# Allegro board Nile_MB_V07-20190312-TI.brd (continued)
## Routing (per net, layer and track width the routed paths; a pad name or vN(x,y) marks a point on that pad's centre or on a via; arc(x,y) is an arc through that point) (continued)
V5P0_HUB: length 34.7
  TOP w0.4: C4607.1 31.14,26.41 U3702.1
  INNER LAYER 5 w0.3: v3(30.79,26.17) 30.76,26.17 30.76,26.16 30.71,26.11 28.21,26.11 27.86,25.76 20.76,25.76 20.48,26.04 v3(15.58,26.04)
  INNER LAYER 7 w0.3: v3(15.09,11.32) 15.09,11.59 15.73,12.23 15.73,17.68 17.43,19.38 17.43,21.88 15.68,23.63 15.68,25.94 v3(15.58,26.04)
  INNER LAYER 8 w0.3: v1(14.75,11.38) 14.93,11.38 14.93,11.38 14.99,11.38 15.03,11.33 15.03,11.32 v3(15.09,11.32)
  BOTTOM w0.076: R6678.1 14.75,10.78
  BOTTOM w0.3: 14.75,10.78 v1(14.75,11.38)
  vias: v5(31.01,24.81) v5(31.16,25.11) v5(31.36,25.46) v5(31.36,24.81) v6(31.01,24.81) v6(31.16,25.11) v6(31.36,25.46) v6(31.36,24.81)
VBAT_EX: length 85.3
  TOP w0.076: R6658.2 31.38,35.81
  TOP w0.3: 32.61,19.45 32.63,19.45 v6(32.66,19.41) ; 31.38,35.81 32.92,35.81 33.07,35.66 33.36,35.66 33.36,35.66 v6(33.84,35.19) ; 3.68,17.66 v6(3.68,18.26) v6(3.68,18.86) 3.73,18.81 ; 3.68,17.66 3.68,16.41 5.85,16.41 ; 3.68,17.66 3.83,17.51 5.85,17.51 ; 5.85,18.61 5.65,18.81
  INNER LAYER 3 w0.3: v6(33.84,35.19) 34.03,34.99 34.13,34.99 36.27,32.85 39.47,32.85 39.81,32.51 39.81,32.5 v3(39.8,32.5) ; 17.63,15.73 v3(17.48,15.58) 16.83,15.58 16.43,15.18 v3(16.43,14.08) ; v6(4.56,18.81) 4.91,18.81 5.56,19.46 5.56,21.12 5.35,21.34 5.35,39.94 v3(6.21,40.81) ; v3(32.71,17.46) 32.71,17.86 32.65,17.92 32.65,18.62 32.66,18.63 v6(32.66,19.41)
  INNER LAYER 8 w0.3: v1(7.01,40.57) 6.77,40.81 v3(6.21,40.81) ; 40.03,32.26 v3(39.8,32.5) ; v3(32.71,17.46) 32.95,17.7 32.95,17.75 v2(33.49,18.29) ; 22.78,18.29 v3(21.11,19.96) ; v1(17.2,15.78) 17.4,15.58 v3(17.48,15.58) ; v1(16.58,13.6) 16.58,13.93 v3(16.43,14.08)
  INNER LAYER 8 w0.4: 33.16,18.29 24.2,18.29 ; 34.19,17.59 v2(33.49,18.29)
  INNER LAYER 8 w0.8: 33.16,18.29 v2(33.49,18.29) 37.18,18.29 39.94,15.54 39.94,15.06 39.99,15.01 v1(40.46,15.01)
  INNER LAYER 9 w0.8: v1(41,15.56) 41,16.36 40.96,16.4
  INNER LAYER 9 w1: 40.96,16.4 40.96,20.31
  BOTTOM w0.076: 41.15,14.87 41.15,14.86 41.25,14.77 41.38,14.77 41.48,14.86 41.48,14.87 41.74,14.87 41.86,14.75
  BOTTOM w0.15: 20.78,22.11 21.53,22.11 21.58,22.16 ; 21.58,22.16 21.46,22.16 21.31,22.31 21.31,23.01 ; 21.58,22.16 v1(21.81,22.16) ; C6216.1 21.61,20.76 21.36,20.51 v1(21.31,20.51)
  BOTTOM w0.3: C6274.2 20.75,23.23 C418.1 20.35,23.65 20.35,23.88 ; 20.35,23.88 20.35,24.62 20.33,24.63 U2.7 ; 20.35,23.88 19.9,24.33 C6234.1 19.93,24.45 U2.8 ; U3708.4 17.77,15.28 v1(17.77,15.78) v1(17.2,15.78) ; U3708.2 16.58,13.92 v1(16.58,13.6)
  BOTTOM w1: v1(40.86,14.3) 41.57,14.3
  vias: v1(21.34,21.31) v1(21.34,20.86) v1(21.56,21.41) v1(21.56,21.01) v1(21.61,20.66) v1(21.91,21.36) v1(21.96,20.91) v1(21.96,20.51) v1(40.46,15.41) v1(40.46,14.66) v1(40.46,14.31) v1(40.46,13.96) v1(40.46,13.66) v1(40.86,15.26) v1(40.86,14.96) v1(40.86,14.66) v1(40.86,13.96) v1(40.86,13.66) v1(41.28,15.32) v1(41.21,14.66) v1(41.21,14.36) v1(41.21,14.01) v1(41.21,13.66) v1(41.31,14.93) v1(41.56,14.16) v1(41.61,14.56) v1(41.61,13.76) v2(21.34,21.31) v2(21.34,20.86) v2(21.41,22.11) v2(21.56,21.41) v2(21.56,21.01) v2(21.61,20.66) v2(21.91,21.36) v2(21.96,20.91) v2(21.96,20.51) v2(22.96,20.96) v2(22.96,20.61) v2(32.76,18.26) v2(32.81,18.66) v2(33.11,18.31) v2(33.26,18.66) v2(33.71,18.66) v2(33.91,18.26) v2(34.11,18.66) v2(40.46,15.41) v2(40.46,14.66) v2(40.46,14.31) v2(40.46,13.96) v2(40.46,13.66) v2(40.86,15.26) v2(40.86,14.96) v2(40.86,14.66) v2(40.86,13.96) v2(40.86,13.66) v2(41.21,14.66) v2(41.21,14.36) v2(41.21,14.01) v2(41.21,13.66) v2(41.56,14.16) v2(41.61,14.56) v2(41.61,13.76) v3(20.31,19.86) v3(20.71,19.96) v3(20.91,20.31) v3(22.38,21.73) v3(22.41,21.36) v3(22.46,20.96) v5(2.81,14.16) v5(2.81,13.76) v5(3.16,14.16) v5(3.21,13.81) v5(3.56,14.16) v5(3.56,13.81) v5(3.66,17.66) v5(3.66,17.01) v5(3.66,16.41) v5(4.16,18.81) v5(4.16,18.26) v5(4.11,17.61) v5(4.16,17.06) v5(4.11,16.46) v5(4.51,18.26) v5(4.56,17.56) v5(4.56,17.16) v5(4.61,16.51) v6(2.81,14.16) v6(2.81,13.76) v6(3.16,14.16) v6(3.21,13.81) v6(3.56,14.16) v6(3.56,13.81) v6(3.66,17.66) v6(3.66,17.01) v6(3.66,16.41) v6(4.16,18.81) v6(4.16,18.26) v6(4.11,17.61) v6(4.16,17.06) v6(4.11,16.46) v6(4.51,18.26) v6(4.56,17.56) v6(4.56,17.16) v6(4.61,16.51)
VBATT: length 30.7
  INNER LAYER 8 w0.8: v1(25.11,24.96) 25.11,25.26 26.63,26.78 26.63,33.74 24.76,35.61 v2(24.76,35.86)
  INNER LAYER 8 w1.4: v1(23.91,22.18) 23.98,22.25 24.76,22.25 24.9,22.11 26.13,22.11 28.13,20.11 38.12,20.11
  BOTTOM w0.8: v1(23.91,22.18) 23.91,23.76 v1(25.11,24.96)
  vias: v1(23.46,22.56) v1(23.46,22.26) v1(23.46,21.91) v1(23.81,22.56) v1(23.86,21.86) v1(24.26,22.56) v1(24.26,22.26) v1(24.26,21.91) v1(24.41,36.31) v1(24.46,35.81) v1(24.76,36.31) v1(24.76,35.81) v1(25.11,36.31) v1(25.11,35.81) v1(25.11,26.11) v1(25.11,25.71) v1(25.11,25.36) v2(23.46,22.56) v2(23.46,22.26) v2(23.46,21.91) v2(23.81,22.56) v2(23.86,21.86) v2(24.26,22.56) v2(24.26,22.26) v2(24.26,21.91) v2(24.41,36.31) v2(24.46,35.86) v2(24.76,36.31) v2(25.11,36.31) v2(25.11,35.86) v2(25.11,26.11) v2(25.11,25.71) v2(25.11,25.36)
VBUS2_OUT_5V_EN: length 17.1
  INNER LAYER 5 w0.076: v3(18.16,40.66) 18.7,40.12 20.85,40.12 21.32,39.65 31.62,39.65 31.62,39.66 31.81,39.66 31.81,39.65 32.32,39.65 32.32,39.66
  INNER LAYER 8 w0.076: v3(18.16,40.66) 18.16,40.86 18.81,41.51 v1(18.91,41.51)
  BOTTOM w0.076: U3704.4 18.76,41.41 18.86,41.51 v1(18.91,41.51) R147.1
VBUS_OUT_5V: length 17.1
  INNER LAYER 8 w1: v1(8.41,40.71) 8.41,40.74 8.79,41.11 11.21,41.11 17.31,47.21 v1(17.31,48.01)
  BOTTOM w0.5: USB1.1 19.42,51.15 17.68,49.42 17.42,49.42 TP68.1 v1(17.31,48.01)
  vias: v1(8.16,41.51) v1(8.21,41.16) v1(8.21,40.31) v1(8.56,41.51) v1(8.61,41.16) v1(8.61,40.36) v1(8.91,40.86) v1(8.96,41.51) v1(9.11,41.21) v1(9.16,40.71) v1(9.11,40.31) v1(16.91,48.06) v1(17.06,48.56) v1(17.11,49.31) v1(17.56,48.56) v1(17.61,49.31) v1(17.71,48.06) v1(17.86,48.86) v1(17.91,49.76) v2(8.16,41.51) v2(8.21,41.16) v2(8.21,40.31) v2(8.56,41.51) v2(8.61,41.16) v2(8.61,40.36) v2(8.91,40.86) v2(8.96,41.51) v2(9.11,41.21) v2(9.16,40.71) v2(9.11,40.31) v2(16.91,48.06) v2(17.06,48.56) v2(17.11,49.31) v2(17.56,48.56) v2(17.61,49.31) v2(17.71,48.06) v2(17.86,48.86) v2(17.91,49.76) v2(18.41,49.26)
VDD11D_PM: length 1.4
  BOTTOM w0.203: C273.1 26.75,13.02 26.34,12.6 U18.43
VDD13_BT: length 33.1
  INNER LAYER 8 w0.1: v8(26.34,10.56) 26.09,10.56 26.04,10.51 26.03,10.51 25.87,10.34 25.25,10.34 25.13,10.46 24.87,10.46 24.76,10.34 24.66,10.34
  INNER LAYER 8 w0.127: v8(25.59,9.84) 25.56,9.82 25.17,9.82
  INNER LAYER 8 w0.152: 24.33,9.66 24.47,9.8 25.15,9.8 25.17,9.82
  INNER LAYER 8 w0.2: 24.33,9.66 23.93,9.26 23.44,9.26 v1(23.43,9.27)
  INNER LAYER 8 w0.25: 24.66,10.34 24.42,10.34 23.64,9.56 23.64,9.48 v1(23.43,9.27)
  INNER LAYER 8 w0.3: 22.59,14.97 22.65,14.91 v8(23.29,14.91)
  INNER LAYER 8 w0.35: v8(21.85,8.22) 21.6,8.22 21.54,8.29 21.22,8.29 20.9,8.61 20.9,8.67 ; 20.9,8.67 20.96,8.67 v8(21.55,8.07) 21.55,7.97 21.67,7.86 21.75,7.94 v8(21.83,7.94) ; 20.9,8.67 20.54,9.03 20.54,12.72 20.39,12.87 20.39,13.23 20.54,13.39 20.54,14.2 20.49,14.25 20.49,14.47 20.51,14.48 20.51,14.56 20.91,14.96 22.59,14.96 22.59,14.97 ; 22.59,14.97 22.65,15.03 22.65,15.12 22.59,15.18 22.59,14.97
  INNER LAYER 9 w0.2: v1(23.36,8.7) 23.6,8.94 23.86,8.94 24.47,9.55 24.47,9.64 24.65,9.82 24.7,9.82 24.7,9.82 24.94,9.82 24.95,9.82 v4(25.1,9.82)
  INNER LAYER 9 w0.3: 23.41,14.63 23.57,14.8 23.57,14.89 v8(23.69,14.89) ; 23.57,14.04 23.57,14.59 23.31,14.85
  INNER LAYER 9 w0.35: v1(24.6,13.61) 24,13.61 23.57,14.04
  BOTTOM w0.076: C265.1 25.31,13.61 ; C264.1 23.39,9.92
  BOTTOM w0.2: v4(25.1,9.82) 25.07,9.82 ; 23.4,9.31 23.71,9.62 ; 24.35,10.06 U18.5 ; 23.37,9.27 23.36,9.27 23.36,9.08 ; 23.39,9.92 23.48,9.92 23.65,10.1
  BOTTOM w0.203: 25.7,12.31 25.84,12.16 U18.29 ; 23.71,9.62 23.9,9.62 24.35,10.06 ; U18.4 24.65,10.56 24.64,10.55 24.64,10.55 24.59,10.5 24.29,10.5 23.89,10.1 23.65,10.1
  BOTTOM w0.3: v8(23.29,14.91) 23.38,15 R100.2
  BOTTOM w0.35: 25.7,12.31 25.7,12.7 25.63,12.76 25.63,13.21 25.31,13.53 25.31,13.61 25.31,13.61 v1(24.6,13.61) ; v1(23.36,8.7) 23.36,9.08 23.37,9.09 23.37,9.27 23.4,9.31 23.4,9.91 23.39,9.92
  BOTTOM w0.4: v1(23.36,8.7) 23.36,7.98 v1(23.3,7.93) 21.92,7.93 C258.1
  vias: v8(23.35,15.13) v8(23.65,15.14)
VDD33_FEM: length 32.3
  INNER LAYER 5 w0.3: v3(28.2,11.36) 28.25,11.31 ; 24.03,8.23 24.03,8.22 24.35,7.89 24.35,7.63
  INNER LAYER 5 w0.35: 28.25,11.31 29.35,10.22 29.35,9.02 28.01,7.68 26.86,7.68 26.85,7.69 26.85,7.5 ; v7(24.33,7.43) 24.28,7.48 24.28,7.56 24.35,7.63 24.35,7.62 24.91,7.06 ; 24.91,7.06 26.5,7.06 26.85,7.41 26.85,7.5 ; 24.91,7.06 24.72,7.06 v3(24.54,6.88) ; 26.85,7.5 v7(26.83,7.48)
  INNER LAYER 5 w0.4: 24.04,8.24 24.03,8.23 23.9,8.36 23.9,12.44 v7(23.29,13.05)
  INNER LAYER 8 w0.127: v8(26.83,9.57) 26.83,9.45 26.85,9.43 26.85,9.21 26.83,9.2 26.83,8.82 26.85,8.8 26.85,8.56 26.83,8.54 26.83,8.38 26.69,8.24 26.69,8.17 26.52,8 26.52,7.98 26.55,7.96
  INNER LAYER 8 w0.2: v1(24.38,6.61) 24.4,6.59 v1(24.4,6.31) ; v3(24.54,6.88) 24.54,7.05 24.38,7.21 24.38,7.59 24.34,7.63 ; v8(25.84,9.57) 25.27,9.57 25.1,9.4 25.1,8.96
  INNER LAYER 8 w0.203: 26.5,7.87 26.59,7.96 ; v8(23.36,12.61) 23.36,12.98 v7(23.29,13.05)
  INNER LAYER 8 w0.3: 25.1,8.96 24.35,8.22 24.35,7.68 24.4,7.63 24.38,7.62 24.35,7.62 24.35,7.63 24.34,7.63 24.28,7.57 ; 24.28,7.57 24.28,7.68 24.04,7.93 v1(23.95,7.93) 23.95,8.26 24.04,8.34 ; 24.28,7.57 24.28,7.48 v7(24.33,7.43) ; v3(28.2,11.36) 28.35,11.21 v1(28.35,10.92) ; v4(26.59,7.96) 26.56,7.96 ; 24.38,8.19 24.55,8.02 v1(24.55,7.93)
  INNER LAYER 8 w0.4: v4(26.59,7.96) 26.59,7.95 26.83,7.7 v7(26.83,7.48) ; 24.56,6.6 24.56,6.86 v3(24.54,6.88)
  BOTTOM w0.076: 28.36,10.83 28.37,10.82 C270.1 ; 26.59,7.97 v4(26.59,7.96) C257.1 ; C272.1 23.9,11.93
  BOTTOM w0.1: U18.71 28,11.05 28.23,10.82 28.36,10.82
  BOTTOM w0.2: U18.55 26.58,7.98 26.59,7.97
  BOTTOM w0.203: U18.2 24.59,11.55 ; 23.39,12.58 v8(23.36,12.61)
  BOTTOM w0.25: 28.36,10.82 28.36,10.83 28.16,11.03 27.93,11.03 27.9,11.05
  BOTTOM w0.3: C255.1 23.9,12.01 23.9,11.93 ; v1(23.95,7.93) v1(24.55,7.93)
  BOTTOM w0.35: 24.59,11.55 24.5,11.55 24.3,11.75
  BOTTOM w0.4: 23.33,12.58 23.39,12.58 24.01,11.96 24.01,11.93 24.02,11.92 24.14,11.92 24.3,11.75
  BOTTOM w0.6: C255.1 23.3,12.61 23.3,13.49 R102.2
  vias: v8(23.2,13.52) v8(23.25,13.82)
VDD_CAP: length 14.7
  INNER LAYER 9 w0.076: v1(30.73,37.99) 30.76,37.99 30.76,38.02 30.9,38.02 v2(30.9,38.17)
  BOTTOM w0.3: 11.91,34.41 U4619.6 ; 11.91,34.41 12.44,34.41 12.66,34.19 14.46,34.19 ; 11.91,34.41 11.86,34.36 11.86,33.72 ; C6300.1 15.81,37.16 16.26,37.61 ; C6270.1 16.48,38.11 16.62,37.97
  BOTTOM w1: 14.46,34.19 14.46,34.26 16.26,36.06 16.26,37.61 16.62,37.97 L3709.1
  vias: v1(17.91,38.16) v1(17.91,37.66) v1(18.36,38.16) v1(18.36,37.66) v1(18.81,38.21) v1(18.81,37.66) v1(19.36,37.61) v1(19.41,38.16) v1(19.86,38.16) v1(19.86,37.61) v1(20.36,38.16) v1(20.41,37.61) v1(20.96,38.21) v1(20.96,37.61) v1(30.5,38.17) v1(30.5,37.79) v1(30.5,37.42) v1(30.9,37.77) v1(30.9,37.42) v1(31.3,38.17) v1(31.3,37.77) v1(31.3,37.42) v1(31.65,38.17) v1(31.65,37.77) v1(31.65,37.42) v1(32,38.17) v1(32,37.77) v1(32,37.42) v2(17.91,38.16) v2(17.91,37.66) v2(18.36,38.16) v2(18.36,37.66) v2(18.81,38.21) v2(18.81,37.66) v2(19.36,37.61) v2(19.41,38.16) v2(19.86,38.16) v2(19.86,37.61) v2(20.36,38.16) v2(20.41,37.61) v2(20.96,38.21) v2(20.96,37.61) v2(30.5,38.17) v2(30.5,37.79) v2(30.5,37.42) v2(30.9,37.77) v2(30.9,37.42) v2(31.3,38.17) v2(31.3,37.77) v2(31.3,37.42) v2(31.65,38.17) v2(31.65,37.77) v2(31.65,37.42) v2(32,38.17) v2(32,37.77) v2(32,37.42)
VDDIO_954_EN: length 32.3
  INNER LAYER 3 w0.076: v3(16.91,24.46) 16.91,24.66 18.41,26.16 18.41,36.71 19.21,37.51 19.21,38.31 20.36,39.46 v3(20.46,39.46)
  INNER LAYER 5 w0.076: 30.45,39.42 30.44,39.41 20.51,39.41 v3(20.46,39.46)
  INNER LAYER 8 w0.076: v3(16.91,24.46) 16.91,24.32 17.42,23.81 20.52,23.81 v1(21.1,24.38)
  BOTTOM w0.076: U2.6 20.73,24.75 v1(21.1,24.38)
VIN_8V5: length 19.5
  INNER LAYER 8 w0.8: v2(29.27,44.36) 31.14,46.23 40.53,46.23
  INNER LAYER 9 w0.8: v1(27.8,40.8) 27.8,40.92 29.06,42.18 29.06,44.15 v2(29.27,44.36)
  BOTTOM w0.5: 28.18,41.02 27.9,40.74
  BOTTOM w0.6: B34.1 25.66,40.82 C438.1 27.79,40.82 ; 27.59,41.02 27.79,40.82 ; 27.79,40.82 v1(27.8,40.8)
  vias: v1(27.28,40.6) v1(27.38,40.49) v1(27.79,40.46) v1(28.16,40.47) v1(28.35,40.62) v2(28.98,44.33) v2(29.23,44.08) v2(29.43,44.73) v2(29.64,44.48)
ANT_2G_CH0: length 1.6
  BOTTOM w0.076: C288.2 35.02,6.27
  BOTTOM w0.12: FL1.3 36.2,7 arc(36.03,6.58) L29.2 35.35,6.4 arc(35.17,6.37) 35.02,6.27
BB_PLL_REF_CLK: length 20.2
  INNER LAYER 3 w0.076: v7(30.06,14.38) 31.22,14.38 33.26,16.41 33.26,16.61 34.16,17.51 34.16,18.38 35.96,20.18 35.96,22.66 v3(35.97,22.67)
  INNER LAYER 5 w0.076: v3(35.97,22.67) 36.31,22.33 36.75,22.33 41.96,17.12
  INNER LAYER 8 w0.076: v9(29.85,14.81) 30.06,14.6 v7(30.06,14.38)
BIST_954: length 2.1
  BOTTOM w0.076: R200.1 17.39,23.7
  BOTTOM w0.1: U33.6 16.92,24.95 17.19,24.69 17.19,23.94 17.39,23.73 17.39,23.7
BT_FM_SB_CLK: length 37.5
  INNER LAYER 3 w0.076: v3(29.36,22.61) 29.21,22.46 29.21,21.23 23.89,15.91 23.89,14.92 24.86,13.95 v7(24.98,13.95)
  INNER LAYER 5 w0.076: 37.37,36.12 36.73,35.48 35.2,35.48 34.25,36.43 30.74,36.43 v7(30.61,36.31)
  INNER LAYER 7 w0.076: v7(30.61,36.31) 30.46,36.16 30.46,36.06 30.31,35.91 30.31,35.78 29.76,35.24 29.76,34.41 27.58,32.23 27.58,23.69 28.16,23.11 28.96,23.11 29.36,22.71 v3(29.36,22.61)
  INNER LAYER 8 w0.076: v7(24.98,13.95) 24.98,13.89 25.62,13.25 25.62,12.57 25.61,12.56 25.61,11.81 v8(25.59,11.8)
BT_FM_SB_DATA: length 39.8
  INNER LAYER 3 w0.076: v7(27.14,13.38) 27.06,13.38 26.78,13.1 25.63,13.1 25.2,13.53 25.05,13.53 25.05,13.53 24.97,13.53 23.73,14.77 23.73,15.97 29.05,21.29 29.05,22.42 v3(28.86,22.61)
  INNER LAYER 5 w0.076: 37.48,35.79 36.75,35.06 36.62,35.06 36.62,35.07 35.06,35.07 34.21,35.92 34.2,35.92 34.16,35.96 32.04,35.96 31.99,35.92 31.16,35.92
  INNER LAYER 5 w0.1: v7(29.6,35.5) 30.75,35.5 30.79,35.54 30.79,35.7 30.98,35.88 31.13,35.88 31.16,35.92
  INNER LAYER 7 w0.076: v7(29.6,35.5) 29.51,35.42 29.51,34.71 27.46,32.66 27.46,32.32 27.43,32.29 27.43,23.63 28.45,22.61 v3(28.86,22.61)
  INNER LAYER 8 w0.076: v7(27.14,13.38) 27.14,13.27 27.43,12.99 27.43,12.99 27.62,12.79 v8(27.62,12.75)
  BOTTOM w0.076: v8(27.62,12.75) 27.55,12.75 27.08,12.28 U18.63
CAM2_VDD: length 33.7
  INNER LAYER 5 w0.4: v3(9.56,29.71) 14.83,29.71 15.78,30.67 v3(17.51,30.67)
  INNER LAYER 8 w0.3: v3(17.51,30.67) 17.1,30.67 v8(17,30.77)
  INNER LAYER 8 w0.4: v3(9.56,29.71) 9.56,29.73 9.25,29.73 v1(8.95,30.03) 8.83,30.16 8.01,30.16 6.68,28.83 6.68,28.76 6.46,28.54 6.39,28.54 6.24,28.39 6.24,25.15 6.56,24.82 v1(6.56,22.66) ; v8(17,30.47) v8(17,30.77)
  INNER LAYER 8 w0.8: 20.11,28.41 17.86,30.67 v3(17.51,30.67) 17.41,30.77 v8(17,30.77)
  BOTTOM w0.076: 18.02,27.25 18.03,27.26
  BOTTOM w0.3: 18.03,27.87 18.75,27.87 19.08,27.53 19.95,27.53 C116.1 20.33,27.12 ; 18.03,27.87 R20.2 ; 18.03,27.87 18.03,27.26 18.04,27.25 ; 20.33,27.12 U2.2 ; 20.33,27.12 19.93,26.72 U2.1 19.08,26.28 C115.1 19.09,26.38 19.09,27.03 18.87,27.25 18.04,27.25 ; v8(17,30.47) B2.2 ; 18.04,27.25 R21.2 ; 20.41,26.81 20.52,26.7 20.54,26.71 20.93,26.71 21.13,26.51 U2.4 ; B3.2 6.61,22.65 6.6,22.66 v1(6.56,22.66) ; 17,30.62 v8(17,30.77)
  vias: v1(18.88,26.68) v1(18.88,26.38) v1(19.23,26.68) v1(19.23,26.38) v1(20.31,27.13) v2(18.88,26.68) v2(18.88,26.38) v2(19.23,26.68) v2(19.23,26.38) v2(20.31,27.13)
CAM_MCLK2: length 19.7
  INNER LAYER 5 w0.076: v3(18.41,24.51) 19.26,24.51 19.64,24.13 25.29,24.13 28,21.43 36.46,21.43
  INNER LAYER 8 w0.076: v1(18.09,24.32) 18.22,24.32 v3(18.41,24.51)
CCI_I2C_SCL1: length 25.3
  INNER LAYER 5 w0.076: v3(17.81,27.66) 18.01,27.66 19.85,29.5 25.97,29.5 27.2,28.26 30.72,28.26 30.91,28.06 32.91,28.06 34.66,26.31 34.66,23.71 35.06,23.31 36.48,23.31
  INNER LAYER 8 w0.15: v3(17.81,27.66) 17.81,27.61 v1(17.41,27.21)
  BOTTOM w0.15: U33.2 17.12,26.95 17.41,27.25 17.41,27.21 v1(17.41,27.21)
CCI_I2C_SDA1: length 32.7
  INNER LAYER 5 w0.076: 41.82,18.23 36.55,23.5 35.16,23.5 34.82,23.85 34.82,26.37 32.93,28.26 30.93,28.26 30.78,28.41 27.26,28.41 26.03,29.65 19.7,29.65 18.29,28.24 v3(17.56,28.24)
  INNER LAYER 8 w0.15: v3(17.56,28.24) 17.4,28.08 v1(17.4,27.87)
  BOTTOM w0.076: v1(17.4,27.87) 17.03,27.5 17.02,27.5 16.97,27.45 U33.1
DC_IN: length 25.8
  INNER LAYER 7 w0.2: v7(29.68,46.45) 29.55,46.45 28.36,45.26 28.36,42.81 23.69,38.14 23.69,37.79 v2(23.66,37.76)
  INNER LAYER 8 w0.2: v7(29.68,46.45) 29.77,46.45 30.45,47.13 31.1,47.13 31.1,47.13 31.35,47.13 31.35,47.13 41.09,47.13
  INNER LAYER 9 w0.2: v1(23.98,38.76) 23.98,38.07 v2(23.66,37.76)
  BOTTOM w0.076: C6271.1 v1(23.98,38.76) ; R6579.2 24.55,38.76
  BOTTOM w0.3: v1(23.98,38.76) 24.55,38.76 24.55,37.92 Q2710.1
FAULT_N: length 19.4
  INNER LAYER 3 w0.076: v7(32.9,24.49) 33.1,24.49 33.51,24.91 33.51,25.41 34.09,25.98 34.09,27.52 31.76,29.85 31.76,30.06 31.75,30.07 31.75,33.54 31.75,33.67 31.63,33.79 31.63,36.62 31.54,36.71 31.36,36.89 31.36,39.91 v7(31.96,40.51)
  INNER LAYER 5 w0.076: v7(31.96,40.51) 32.11,40.36
  INNER LAYER 8 w0.076: v8(31.82,24.39) 31.88,24.33 32.73,24.33 v7(32.9,24.49)
IDX_954: length 1.8
  BOTTOM w0.076: R199.1 8.17,27.75
  BOTTOM w0.25: U33.35 8.97,26.95 8.17,27.75
KEY_VOLP_N: length 35.2
  INNER LAYER 5 w0.076: v3(5.76,21.51) 5.76,24.01 8.79,27.03 14.84,27.03 14.98,27.17 15.48,27.17 15.48,27.17 18.37,27.17 18.54,27.33 21.04,27.33 21.29,27.59 29.44,27.59 30.29,26.73 31.74,26.73 31.83,26.64 v7(32,26.64)
  INNER LAYER 8 w0.076: v1(6.54,20.76) 6.51,20.76 ; 6.51,20.76 v3(5.76,21.51) ; 6.51,20.76 6.51,20.66 5.98,20.13 5.43,20.13 4.4,19.1 v1(4.4,18.93) ; v7(32,26.64) 31.82,26.45 v1(31.82,26.29)
LED_EN: length 11.6
  INNER LAYER 3 w0.076: v6(31.18,32.46) 31.16,32.45 31.16,29.71 31.26,29.61 v3(31.26,29.51)
  INNER LAYER 5 w0.076: v3(31.26,29.51) 31.36,29.51 31.71,29.16 32.84,29.16 37.27,24.74 37.27,24.13
LNA_EN_5G_CH0: length 15.2
  INNER LAYER 5 w0.076: v3(25,6.32) 25.06,6.26 27.13,6.26 27.13,6.26 27.38,6.26 27.38,6.26 28.25,6.26 28.82,6.83 29.58,6.83 29.78,6.63 30.63,6.63 31.23,7.23 31.23,7.27 v3(33.55,7.27)
  INNER LAYER 8 w0.076: v3(33.55,7.27) 33.74,7.45 v1(33.74,7.72)
  INNER LAYER 8 w0.1: v3(25,6.32) 25.4,6.72 25.4,8.1 25.55,8.25 25.55,8.42 26.09,8.96 26.09,10.08 26.11,10.1 v8(26.11,10.27)
  BOTTOM w0.1: U22.6 33.03,8.09 33.15,7.97 33.15,7.96 33.3,7.82 33.3,7.82 33.4,7.72 v1(33.74,7.72) ; U18.39 26.11,10.29 26.11,10.27 v8(26.11,10.27)
LPI_UART_1_RX: length 40.9
  INNER LAYER 5 w0.076: v7(26.86,35.16) 27.07,34.95 30.47,34.95 30.78,35.25 34.43,35.25 34.94,34.74 36.87,34.74 37.62,35.49
  INNER LAYER 7 w0.076: v7(22.15,11.17) 22.25,11.26 22.25,11.52 22.55,11.82 22.55,19.59 23.17,20.2 23.17,20.32 23.17,23.52 23.08,23.61 22.55,24.13 22.55,25.54 25.85,28.83 25.85,30 25.86,30.02 25.86,33.76 26.86,34.76 v7(26.86,35.16)
  INNER LAYER 8 w0.076: v2(22.53,11.28) 22.27,11.28 v7(22.15,11.17)
  INNER LAYER 9 w0.076: v2(22.53,11.28) 22.65,11.16 v1(22.83,11.16)
  BOTTOM w0.064: 24.85,11.01 U18.3
  BOTTOM w0.076: v1(22.83,11.16) 23.03,10.97 24.27,10.97 24.31,10.92 24.49,10.92 24.58,11.01 24.85,11.01
LPI_UART_1_TX: length 41.6
  INNER LAYER 5 w0.076: v3(26.36,35.21) 26.36,35.16 26.8,34.72 30.46,34.72 30.85,35.1 34.36,35.1 34.88,34.58 36.93,34.58 37.69,35.34
  INNER LAYER 7 w0.076: v3(26.36,35.21) 26.16,35.01 26.16,34.46 25.69,33.99 25.69,28.89 22.39,25.59 22.39,24.08 23.01,23.46 23.01,20.26 22.39,19.64 22.39,15.39 22.4,15.38 22.4,12.81 21.95,12.37 v7(21.95,12.28)
  INNER LAYER 8 w0.076: v8(25.59,11.3) 25.11,11.3 25.08,11.32 24.98,11.32 24.73,11.57 24.73,11.58 24.64,11.67 24.23,11.67 24.15,11.75 v2(24.15,11.76) ; v7(21.95,12.28) 22.18,12.28 22.39,12.07 v2(22.65,12.07)
  INNER LAYER 9 w0.076: v2(24.15,11.76) 24.15,11.75 23.88,11.75 23.62,12.02 22.7,12.02 v2(22.65,12.07)
MIPI_CSI1_CLK_M: length 33.9
  INNER LAYER 5 w0.076: v7(18.35,21.49) 18.48,21.37 18.93,21.37 19.05,21.49 19.05,22.5 19.27,22.72 19.84,22.72 20.05,22.5 20.05,21.32 19.55,20.81 19.55,20.57 19.95,20.57 20.45,21.07 20.45,22.45 20.67,22.67 21.19,22.67 21.41,22.45 21.41,20.8 22.09,20.12 36.37,20.12 41.92,14.57
  INNER LAYER 8 w0.06: v9(18.02,21.6) 18.24,21.6 v7(18.35,21.49)
MIPI_CSI1_CLK_M_R: length 2
  BOTTOM w0.06: U33.11 16.62,22.45 16.75,22.32 16.9,22.32 17.15,22.07 17.15,21.47 17.2,21.42 17.34,21.42 F2820.4
MIPI_CSI1_CLK_P: length 34.1
  INNER LAYER 5 w0.076: 41.83,14.37 36.29,19.92 22,19.92 21.2,20.72 21.2,22.37 21.1,22.47 20.8,22.47 20.7,22.37 20.7,20.97 20.05,20.32 19.35,20.32 19.3,20.37 19.3,20.92 19.85,21.46 19.85,22.42 19.75,22.52 19.35,22.52 19.25,22.42 19.25,21.41 18.96,21.12 18.5,21.12 18.35,20.97 v7(18.33,20.97)
  INNER LAYER 8 w0.06: v7(18.33,20.97) 18.33,21.08 v9(18.02,21.08)
  BOTTOM w0.06: F2820.2 v9(18.02,21.08)
MIPI_CSI1_CLK_P_R: length 1.9
  BOTTOM w0.06: U33.12 16.59,21.95 16.73,22.09 16.83,22.09 16.95,21.97 16.95,21.4 17.13,21.23 17.35,21.23 17.48,21.1 F2820.3
MIPI_CSI1_L0_DATA_M: length 35.9
  INNER LAYER 5 w0.076: v7(16.55,20.97) 16.55,20.75 16.52,20.72 16.52,20.61 16.76,20.37 17.16,20.37 17.17,20.37 17.48,20.37 17.55,20.44 17.55,21.79 17.48,21.87 16.87,21.87 16.55,22.18 16.55,23.2 16.75,23.4 16.87,23.52 25.2,23.52 27.69,21.02 36.33,21.02 36.45,20.9 42.26,15.09
  INNER LAYER 8 w0.06: v9(16.4,19.56) 16.35,19.61 16.35,20.37 16.55,20.57 v7(16.55,20.97)
MIPI_CSI1_L0_DATA_M_R: length 1.6
  BOTTOM w0.06: F2822.4 16.25,20.21 16.25,20.37 15.65,20.97 15.65,21.21 U33.13
MIPI_CSI1_L0_DATA_P: length 35.8
  INNER LAYER 5 w0.076: v7(16.1,20.67) 16.1,20.74 16.68,20.17 17.08,20.17 17.09,20.16 17.56,20.16 17.76,20.36 17.76,21.87 17.56,22.07 16.95,22.07 16.75,22.27 16.75,23.12 16.95,23.31 25.11,23.31 27.61,20.82 36.25,20.82 42.18,14.88
  INNER LAYER 8 w0.06: v9(15.91,19.55) 16.15,19.79 16.15,20.62 v7(16.1,20.67)
MIPI_CSI1_L0_DATA_P_R: length 1.6
  BOTTOM w0.06: U33.14 15.24,21.08 16.05,20.27 16.05,20.19 F2822.3
MIPI_CSI1_L1_DATA_M: length 35.1
  INNER LAYER 5 w0.076: v7(15.15,20.12) 15.1,20.12 15.1,19.97 14.75,19.62 14.35,19.62 14.01,19.96 14.01,20.17 13.98,20.21 13.76,20.21 13.67,20.11 13.67,19.49 13.77,19.39 15.26,19.39 arc(15.32,19.42) 15.34,19.48 15.34,19.69 arc(15.43,19.78) 15.52,19.69 15.52,19.48 arc(15.61,19.39) 15.7,19.48 15.7,19.67 arc(15.78,19.76) 15.87,19.67 15.87,19.48 arc(15.9,19.42) 15.96,19.39 36.38,19.39 41.76,14.01
  INNER LAYER 8 w0.06: v7(15.15,20.12) 15.15,20.07 15.04,19.95 15.04,19.61 15.1,19.55 v9(15.19,19.55)
MIPI_CSI1_L1_DATA_M_R: length 1.5
  BOTTOM w0.076: F2818.4 15.02,20.22 15.02,20.47 14.65,20.84 14.65,21.21 U33.15
MIPI_CSI1_L1_DATA_P: length 34.3
  INNER LAYER 5 w0.076: v7(14.7,20.22) 14.75,20.17 14.75,19.97 14.65,19.87 14.39,19.87 14.22,20.04 14.22,20.26 14.06,20.41 13.68,20.41 13.46,20.2 13.46,19.41 13.68,19.19 36.3,19.19 41.68,13.81
  INNER LAYER 8 w0.06: v9(14.69,19.55) 14.79,19.55 14.85,19.61 14.85,19.97 14.65,20.17 v7(14.7,20.22)
MIPI_CSI1_L1_DATA_P_R: length 1.5
  BOTTOM w0.076: F2818.3 14.81,20.17 14.81,20.44 14.24,21.01 U33.16
MIPI_CSI1_L2_DATA_M: length 34.3
  INNER LAYER 5 w0.076: v7(11.55,19.92) 11.45,19.82 11.45,19.72 11.65,19.52 11.75,19.52 12.11,19.87 12.45,19.87 12.66,19.67 12.66,19 12.83,18.82 36.11,18.82 41.74,13.19
  INNER LAYER 8 w0.06: v9(11.5,19.57) 11.5,19.87 v7(11.55,19.92)
MIPI_CSI1_L2_DATA_M_R: length 1.4
  BOTTOM w0.076: U33.21 11.74,21.05 11.5,20.81 11.5,20.57 11.35,20.42 11.35,20.23 F2821.4
MIPI_CSI1_L2_DATA_P: length 34.7
  INNER LAYER 5 w0.076: v7(11.05,19.92) 11.2,19.77 11.2,19.62 11.55,19.27 11.79,19.27 12.19,19.67 12.37,19.67 12.45,19.58 12.45,18.92 12.75,18.62 36.03,18.62 41.66,12.99
  INNER LAYER 8 w0.06: v9(11,19.57) 11,19.87 v7(11.05,19.92)
MIPI_CSI1_L2_DATA_P_R: length 1.4
  BOTTOM w0.076: F2821.3 11.19,20.27 11.19,20.48 11.34,20.63 11.34,20.96 11.24,21.06 U33.22
MIPI_CSI1_L3_DATA_M: length 35.4
  INNER LAYER 5 w0.076: v7(10.2,19.22) 10.25,19.17 10.25,19.02 10.35,18.92 10.53,18.92 arc(10.59,18.94) 10.62,19 10.62,19.13 arc(10.71,19.22) 10.79,19.13 10.79,19 arc(10.88,18.92) 10.97,19 10.97,19.13 arc(11.06,19.22) 11.15,19.13 11.15,18.97 arc(11.16,18.93) 11.2,18.92 11.25,18.92 11.41,18.76 12.06,18.76 12.56,18.27 35.8,18.27 41.48,12.59
  INNER LAYER 8 w0.06: v7(10.2,19.22) 10.24,19.25 v9(10.24,19.59)
MIPI_CSI1_L3_DATA_M_R: length 1.5
  BOTTOM w0.076: F2819.4 10.11,20.22 10.11,20.27 10.61,20.77 10.61,20.93 10.74,21.06 U33.23
MIPI_CSI1_L3_DATA_P: length 34.8
  INNER LAYER 5 w0.076: v7(9.73,19.19) 10.25,18.67 10.99,18.67 11.2,18.67 11.31,18.56 11.98,18.56 12.52,18.02 35.71,18.02 41.34,12.39
  INNER LAYER 8 w0.06: v7(9.73,19.19) 9.74,19.2 v9(9.74,19.59)
MIPI_CSI1_L3_DATA_P_R: length 1.5
  BOTTOM w0.076: F2819.3 9.74,20.12 10.37,20.75 10.37,20.95 10.24,21.08 U33.24
MIPI_DSI0_CLK_M: length 10.7
  INNER LAYER 3 w0.07: v7(46.58,41.09) 46.6,41.11 46.6,41.26 46.68,41.34 46.81,41.34 46.92,41.23 46.92,40.52 46.84,40.44 45.26,40.44 45.01,40.19 45.01,39.59 45.29,39.31 47.5,39.31 50.13,36.68
  INNER LAYER 8 w0.07: v9(46.84,41.43) 46.84,41.35 v7(46.58,41.09)
MIPI_DSI0_CLK_P: length 10.8
  INNER LAYER 3 w0.07: 50.33,36.76 47.59,39.51 45.38,39.51 45.21,39.67 45.21,40.11 45.34,40.24 46.92,40.24 47.12,40.44 47.12,41.31 46.9,41.53 46.9,41.54 46.89,41.55 46.7,41.55 46.6,41.66 v7(46.6,41.73)
  INNER LAYER 8 w0.07: v7(46.6,41.73) 46.56,41.7 46.56,41.65 v9(46.34,41.43)
MOD_AP_READY: length 14.2
  TOP w0.076: TP100.1 v6(33.61,19.86)
  INNER LAYER 3 w0.076: v3(35.47,24.03) 35.78,23.72 35.78,23.39 35.36,22.97 35.36,21.71 33.9,20.24 33.9,20.14 v6(33.61,19.86)
  INNER LAYER 5 w0.076: v3(35.47,24.03) 35.38,24.03 35.55,23.86 36.63,23.86 41.92,18.57
MOD_POWER_ON: length 43.3
  INNER LAYER 3 w0.076: v3(13.41,25.71) 13.41,29.26 12.61,30.06 12.61,32.37 13.1,32.86 13.1,35.93 13.8,36.63 v3(13.8,36.82)
  INNER LAYER 5 w0.076: 36.54,21.79 28.06,21.79 25.33,24.53 20.89,24.53 19.88,25.54 13.73,25.54 13.56,25.71 v3(13.41,25.71)
  INNER LAYER 8 w0.076: v1(8.51,36.91) 8.66,36.76 9.21,36.76 9.28,36.7 9.53,36.7 9.59,36.76 13.74,36.76 v3(13.8,36.82)
  BOTTOM w0.076: 8.51,36.9 v1(8.51,36.91) R6537.2
  BOTTOM w0.3: 8.51,36.9 9.58,36.9 Q8.1
MOD_POWER_ON_R: length 27.3
  TOP w0.1: 30.75,35.81 30.75,35.8 29.01,34.06 28.1,34.06 28.05,34.01
  TOP w0.3: 28.05,34.01 28.95,34.01 v6(30.75,35.81)
  INNER LAYER 3 w0.1: v3(27.91,37.26) 28.06,37.41 28.96,37.41 30.56,35.81 v6(30.75,35.81)
  INNER LAYER 5 w0.1: v3(27.91,37.26) 11.76,37.26 v3(11.71,37.31)
  INNER LAYER 8 w0.1: v3(11.71,37.31) 11.91,37.51 v1(11.91,37.81)
MOD_RESET: length 17.6
  TOP w0.1: v5(31.36,20.07) 31.36,21.11 Q2712.1
  INNER LAYER 2 w0.076: v5(31.36,20.07) 32.11,20.82 33.41,20.82 v6(33.64,20.59)
  INNER LAYER 3 w0.076: v3(35.47,24.52) 35.44,24.52 35.17,24.25 35.17,23.3 34.62,22.75 34.62,21.56 v6(33.64,20.59)
  INNER LAYER 5 w0.076: v3(35.47,24.52) 35.48,24.51 35.71,24.51 36.21,24.01 36.69,24.01 37.26,23.45 37.29,23.45 42.02,18.72
MOD_RESET_R: length 23.7
  TOP w0.076: 28.05,37.31 28.19,37.45 31.03,37.45 31.51,36.96 v6(31.66,36.96) ; R6656.2 32.61,20.07 ; Q2712.3 32.16,23.61 32.31,23.76 32.71,23.76 v6(32.81,23.86) ; C437.2 32.01,20.07
  TOP w0.1: 32.61,20.07 32.01,20.07 31.96,20.12 31.96,23.36 Q2712.3
  INNER LAYER 3 w0.076: v6(31.66,36.96) 31.66,36.8 31.78,36.69 31.78,33.85 31.92,33.72 31.92,29.91 34.24,27.58 34.24,25.92 33.67,25.35 33.67,24.84 33.15,24.33 33.15,24.3 32.81,23.96 v6(32.81,23.86)
MOD_RI: length 20.1
  TOP w0.076: 30.36,25.27 R6536.2
  TOP w0.1: v6(30.96,28.5) 30.81,28.35 30.81,26.94 30.36,26.49 30.36,25.27
  INNER LAYER 3 w0.1: v3(31.27,28.56) 31.02,28.56 v6(30.96,28.5)
  INNER LAYER 5 w0.076: 41.85,18.42 36.62,23.65 35.23,23.65 34.97,23.91 34.97,26.44 32.94,28.46 31.37,28.46 v3(31.27,28.56)
MOD_V_BACK: length 3.7
  TOP w0.4: 31.09,16.69 C6366.1
  TOP w0.5: C6366.1 30.61,16.56 29.46,15.41 28.15,15.41 28.05,15.31
MOD_VINT: length 25.1
  TOP w0.076: v6(33.31,36.26) 33.16,36.41 32.66,36.41 32.63,36.45 32.41,36.45 R6663.1
  TOP w0.1: 30.95,17.96 v6(30.95,18.01)
  TOP w0.2: 28.05,17.51 28.76,17.51 29.21,17.96 30.95,17.96
  INNER LAYER 3 w0.1: v6(30.95,18.01) 30.95,20.25 32.11,21.41 32.11,22.71 33.06,23.65 33.06,23.98 33.31,24.24 33.31,24.26 33.66,24.61 34.16,24.61 34.41,24.86 34.41,27.85 33.16,29.1 33.16,31.11 33.78,31.72 33.78,34.38 33.31,34.84 v6(33.31,36.26)
MOD_W_DISABLE: length 7.1
  INNER LAYER 3 w0.076: v3(36.11,24.61) 35.93,24.43 35.93,23.31 35.52,22.89 35.52,21.65 34.05,20.18 34.05,19.35 33.56,18.86 v6(33.56,18.76)
  INNER LAYER 5 w0.076: v3(36.11,24.61) 36.35,24.61
MODE_954: length 2.3
  BOTTOM w0.076: R196.2 9.18,29.46 9.18,29.47 ; 9.58,29.47 R198.1
  BOTTOM w0.25: 9.18,29.47 9.62,29.47 9.62,29.16 10.24,28.55 U33.37
MSS_LTE_COEX_RX: length 9.1
  INNER LAYER 5 w0.076: v7(30.67,11.76) 30.87,11.56 32.25,11.56 34.31,9.51 34.36,9.51 34.9,8.96
  INNER LAYER 8 w0.076: v9(29.09,11.76) 29.2,11.76 29.21,11.76 29.21,11.79 29.35,11.93 29.54,11.93 29.55,11.92 29.86,11.92 30,12.06 30.25,12.06 30.43,11.88 30.43,11.87 30.54,11.76 v7(30.67,11.76)
  BOTTOM w0.076: U18.70 27.61,11.55 27.62,11.53 27.75,11.53 27.75,11.53 27.81,11.53 27.81,11.52 28.39,11.52 28.49,11.62 28.95,11.62 v9(29.09,11.76)
MSS_LTE_COEX_TX: length 10.3
  INNER LAYER 5 w0.076: v7(31.3,12.77) 31.3,12.49 31.7,12.09 31.7,12.09 31.88,11.91 31.88,11.91 31.91,11.88 32.36,11.88 34.43,9.81 34.5,9.81 35.04,9.27
  INNER LAYER 8 w0.076: v8(26.89,11.54) 27.05,11.7 27.6,11.7 28.41,12.52 30.49,12.52 30.69,12.72 31.25,12.72 v7(31.3,12.77)
  BOTTOM w0.076: v8(26.89,11.54) U18.57
PA_EN_5G_CH0: length 9.7
  INNER LAYER 8 w0.076: 33.75,9.08 33.72,9.05 ; 33.75,9.08 v9(33.75,9) ; 33.75,9.08 33.77,9.1 33.77,9.67 31.99,11.45 28.54,11.45 28.51,11.48 28.51,11.49 28.33,11.67 28.08,11.67 27.9,11.49 27.9,11.48 27.81,11.39 27.66,11.39 27.65,11.38 27.59,11.38 27.27,11.05 v8(26.83,11.05)
  BOTTOM w0.1: U22.4 33.25,8.79 arc(33.52,8.85) v9(33.75,9)
PDB_954: length 43
  INNER LAYER 3 w0.076: v3(10.36,38.21) 10.36,36.21 10.01,35.86 10.01,25.71 v3(9.16,24.86)
  INNER LAYER 5 w0.076: 32.26,39.81 32.25,39.81 31.88,39.81 31.87,39.81 31.56,39.81 31.55,39.81 21.38,39.81 20.91,40.27 19.09,40.27 18.3,41.06 13.01,41.06 10.26,38.31 v3(10.36,38.21)
  INNER LAYER 8 w0.076: v2(8.36,23.86) 9.16,24.66 v3(9.16,24.86)
  INNER LAYER 9 w0.076: v1(7.79,23.71) 7.94,23.86 v2(8.36,23.86)
  BOTTOM w0.076: R195.2 7.23,22.66
  BOTTOM w0.25: U33.30 8.96,24.45
  BOTTOM w0.3: 7.23,22.66 7.23,23.15 v1(7.79,23.71) 8.53,24.45 8.96,24.45
PM_RESIN_N: length 40.1
  INNER LAYER 5 w0.076: 13.71,44.86 18.01,44.86 19.65,46.5 22.64,46.5 23.13,46.99 41.31,46.99 41.46,47.14 41.78,47.14 41.93,46.99
  INNER LAYER 5 w0.1: 13.71,44.86 11.16,42.31 10.86,42.31 7.51,38.96 v3(6.76,38.96)
  INNER LAYER 8 w0.1: v3(6.76,38.96) 6.89,38.96 v1(7.06,38.78)
  BOTTOM w0.076: R284.1 6.7,37.91
  BOTTOM w0.1: v1(7.06,38.78) 6.99,38.78 6.7,38.5 6.7,37.91
PON_OUT: length 19.2
  INNER LAYER 3 w0.076: v7(33.1,25.27) 33.94,26.1 33.94,27.46 31.61,29.78 31.61,30 31.6,30.01 31.6,33.6 31.48,33.73 31.48,36.56 31.21,36.82 31.21,39.97 31.6,40.36 31.6,40.58 v7(31.51,40.66)
  INNER LAYER 5 w0.076: v7(31.51,40.66) 31.69,40.66 31.84,40.81 32.09,40.81 32.27,40.64 32.27,40.55
  INNER LAYER 8 w0.076: v7(33.1,25.27) v8(32.87,25.04)
  BOTTOM w0.076: U11.33 v8(32.87,25.04)
QCS_GPIO_76: length 27.9
  INNER LAYER 3 w0.076: v3(11.01,38.51) 10.91,38.41 10.91,38.19 10.91,38.19 10.91,37.94 10.91,37.94 10.91,36.29 10.26,35.64 10.26,24.62 8.77,23.14 v3(8.77,23.1)
  INNER LAYER 5 w0.076: 21.22,39.24 20.94,38.96 11.47,38.96 v3(11.01,38.51)
  INNER LAYER 8 w0.076: v9(8.99,23.33) 8.83,23.17 8.8,23.17 8.77,23.14 v3(8.77,23.1)
  BOTTOM w0.076: v9(8.99,23.33) 9.16,23.5 9.55,23.5 U33.28
QCS_GPIO_77: length 27.4
  INNER LAYER 3 w0.076: v3(9.08,22.72) 10.41,24.05 10.41,35.58 11.06,36.23 11.06,36.36 11.06,38.01 11.12,38.07 v3(11.21,38.07)
  INNER LAYER 5 w0.076: 21.34,38.94 21.06,38.66 12.2,38.66 11.6,38.07 v3(11.21,38.07)
  INNER LAYER 8 w0.076: v9(9.39,22.95) 9.16,22.72 v3(9.08,22.72)
  BOTTOM w0.076: v9(9.39,22.95) U33.27
QCS_GPIO_78: length 27.8
  INNER LAYER 3 w0.076: v3(9.12,22.27) 9.12,22.34 10.56,23.77 10.56,35.52 11.21,36.17 11.21,36.42 11.21,37.6 11.61,38 11.61,38.51 v3(11.56,38.56)
  INNER LAYER 5 w0.076: v3(11.56,38.56) 11.82,38.81 21,38.81 21.28,39.09
  INNER LAYER 8 w0.076: v3(9.12,22.27) 9.16,22.27 9.35,22.45 v9(9.38,22.45)
  BOTTOM w0.076: v9(9.38,22.45) U33.26
QCS_GPIO_91: length 41.7
  INNER LAYER 5 w0.076: v3(6.86,30.36) 7.01,30.36 8,29.37 15.57,29.37 16.21,30.01 18.86,30.01 19.08,29.8 27.78,29.8 27.99,29.58 30.74,29.58 31.46,28.86 32.93,28.86 37.11,24.67 37.11,24.07 41.59,19.59 41.59,19.59
  INNER LAYER 8 w0.076: v1(6.81,29.81) 7.01,30.01 7.01,30.21 v3(6.86,30.36)
  BOTTOM w0.076: R289.1 6.71,28.97 ; 6.84,29.84 D3848.1
  BOTTOM w0.3: D3848.1 6.71,29.73 6.71,28.97
QCS_GPIO_92: length 3.5
  INNER LAYER 5 w0.076: v7(28.06,3.87) 28.06,4.63 28.64,5.21 29.18,5.21 29.27,5.29
  INNER LAYER 8 w0.076: v7(28.06,3.87) 27.9,3.7 27.69,3.7 v1(27.64,3.75)
  BOTTOM w0.076: R288.1 27.56,3.67 v1(27.64,3.75)
QUP6_HCI_UART_CTS_N: length 17.6
  INNER LAYER 5 w0.076: v7(30.79,13.06) 30.88,13.14 31.53,13.14 34.56,10.11 41.96,10.11
  INNER LAYER 8 w0.051: 26.89,11.85 26.89,11.85
  INNER LAYER 8 w0.064: 26.89,11.85 26.6,11.56 26.6,11.44 26.58,11.42 v8(26.58,11.3)
  INNER LAYER 8 w0.076: 26.89,11.85 27.5,11.85 28.05,12.41 28.09,12.41 28.35,12.67 28.36,12.67 28.46,12.77 30.3,12.77 30.35,12.82 30.57,12.82 30.8,13.05 30.8,13.06 v7(30.79,13.06)
QUP6_HCI_UART_RFR_N: length 31.4
  INNER LAYER 3 w0.076: v7(41.83,9.8) 41.82,9.8 41.82,9.83 42.01,10.02 42.01,10.71 49.34,18.03 49.45,18.03 49.73,18.31 49.84,18.31 50.51,18.99 50.51,20.06 51.12,20.67 51.22,20.67
  INNER LAYER 5 w0.076: v7(41.83,9.8) 41.82,9.8 41.82,9.83 41.75,9.9 34.67,9.9 34.65,9.92 34.6,9.92 34.57,9.96 34.5,9.96 31.89,12.57 31.8,12.57 31.75,12.52 31.75,12.5 v7(31.74,12.5)
  INNER LAYER 8 w0.076: v8(27.08,11.3) 27.27,11.3 27.51,11.54 27.59,11.54 27.6,11.55 27.66,11.55 28.48,12.37 30.55,12.37 30.65,12.46 31.7,12.46 v7(31.74,12.5)
QUP6_HCI_UART_RX: length 21.7
  INNER LAYER 3 w0.076: 42.02,8.79 35.31,8.79 34.64,8.12 33.43,8.12 33.33,8.22 31.26,8.22 31.25,8.24 30.88,8.24 30.68,8.43 v3(30.6,8.43)
  INNER LAYER 6 w0.076: v3(24.5,12.02) 25.7,12.02 26.63,11.08 26.63,10.43 28.93,8.14 30.49,8.14 30.6,8.25 v3(30.6,8.43)
  INNER LAYER 8 w0.076: v3(24.5,12.02) 24.5,12.27 v2(24.35,12.42)
  INNER LAYER 9 w0.076: v2(24.35,12.42) 24.4,12.37 24.45,12.17 v1(24.45,12.16)
  BOTTOM w0.076: U18.8 24.74,11.8 24.45,12.09 v1(24.45,12.16)
QUP6_HCI_UART_TX: length 22.4
  INNER LAYER 3 w0.076: v3(31.13,8.54) 31.29,8.38 33.39,8.38 33.49,8.28 34.59,8.28 35.25,8.95 41.96,8.95
  INNER LAYER 5 w0.076: 31.08,8.58 31.13,8.54 v3(31.13,8.54)
  INNER LAYER 6 w0.076: v3(31.13,8.54) 31.13,8.38 30.73,7.98 28.87,7.98 26.48,10.37 26.48,11.02 25.87,11.63 25.1,11.63 v7(25.06,11.67)
  INNER LAYER 8 w0.076: v7(25.06,11.67) 25.22,11.55 v8(25.35,11.55)
  INNER LAYER 9 w0.076: v8(25.35,11.55) 25.32,11.52 23.9,11.52 23.75,11.67 23.6,11.67 v1(23.5,11.77)
  BOTTOM w0.076: R253.2 23.45,11.72 v1(23.5,11.77)
RIN0_M: length 32.8
  INNER LAYER 3 w0.075: v3(13.3,30.28) 13.3,30.35 ; 27.19,54.27 v7(27.35,54.43)
  INNER LAYER 3 w0.076: 13.3,30.35 12.97,30.69 12.97,31.68 13.89,32.6 13.89,35.26 27.19,48.57 27.19,54.27
  INNER LAYER 8 w0.076: v3(13.3,30.28) 13.17,30.28 v1(12.92,30.03)
  INNER LAYER 8 w0.1: v1(27.62,54.81) 27.62,54.7 v7(27.35,54.43)
  INNER LAYER 8 w0.3: 28.84,54.66 27.77,54.66 27.55,54.43 v7(27.35,54.43)
RIN0_P: length 33.3
  INNER LAYER 3 w0.075: v3(13.69,31.15) 13.69,31.2
  INNER LAYER 3 w0.076: v7(28.14,52.19) 27.75,51.79 27.75,48.33 14.45,35.03 14.45,32.28 13.69,31.52 13.69,31.2
  INNER LAYER 8 w0.076: v3(13.69,31.15) 13.19,31.15 v1(12.71,30.66)
  INNER LAYER 8 w0.3: CON2.5 28.37,53.46 v1(28.35,53.48) 28.24,53.38 v1(28.24,52.49) 28.24,52.26 28.17,52.19 v7(28.14,52.19)
  BOTTOM w0.076: v1(12.71,30.66) 12.71,30.52 12.29,30.1 C363.2
SDM_DMIC_CLK2: length 66
  INNER LAYER 5 w0.076: v3(20.36,33.76) 20.36,33.81 20.79,34.24 24.79,34.24 25.09,33.94 30.75,33.94 31.61,34.8 34.22,34.8 34.86,34.16 37,34.16 37.87,35.03 47.26,35.03
  INNER LAYER 7 w0.1: v3(15.62,9.33) 15.78,9.49 15.78,10.4 19.36,13.97 19.36,24.28 18.92,24.72 18.91,24.72 17.77,25.86 16.97,25.86 16.51,26.32 16.51,30 16,30.5 16,31.49 16.61,32.1 18.19,32.1 19.82,33.73 20.34,33.73 v3(20.36,33.76)
  INNER LAYER 8 w0.1: v3(15.62,9.33) 15.62,9.27 14.89,8.54 v1(13.95,8.54)
  INNER LAYER 8 w0.15: v1(9.77,7.62) 9.77,7.71 10.1,8.03 13.58,8.03 13.95,8.4 v1(13.95,8.54)
  BOTTOM w0.1: D33.1 v1(13.95,8.54)
SDM_DMIC_DATA2: length 57.6
  INNER LAYER 5 w0.076: v3(20.43,33.26) 20.43,33.28 21.18,34.03 24.79,34.03 25.03,33.79 30.81,33.79 31.67,34.65 34.16,34.65 34.74,34.06 34.74,34.05 34.78,34.01 37.07,34.01 37.94,34.88
  INNER LAYER 7 w0.1: v3(20.43,33.26) 19.71,33.26 18.32,31.87 16.65,31.87 16.19,31.41 16.19,30.58 16.68,30.09 16.68,26.39 16.96,26.11 17.76,26.11 17.84,26.04 17.85,26.04 18.8,25.09 18.8,25.08 18.98,24.89 18.99,24.89 19.53,24.35 19.53,13.9 16.03,10.4 16.03,9.56 16.11,9.47 v3(16.11,9.33)
  INNER LAYER 8 w0.1: v3(16.11,9.33) 16.03,9.25 16.03,9.08 14.71,7.76 v1(14.71,7.33)
  INNER LAYER 8 w0.15: v1(9.61,5.86) 9.81,5.86 10.78,6.83 12.4,6.83 12.8,7.23 14.08,7.23 14.18,7.33 v1(14.71,7.33)
SLB: length 8
  INNER LAYER 5 w0.076: 34.78,23.11 34.79,23.11 35.04,23.11 35.04,23.11 ; 34.78,23.11 35.04,23.11 ; 34.78,23.11 34.51,23.11 33.89,23.74 33.89,24.31 33.76,24.43 33.76,26.66 v7(33.56,26.86) ; 35.04,23.11 35.06,23.12 36.45,23.12
  INNER LAYER 8 w0.076: v1(33.14,26.52) 33.48,26.86 v7(33.56,26.86)
  BOTTOM w0.076: U11.66 33.13,26.54 33.13,26.52 v1(33.14,26.52)
SLEEP_CLK: length 24.2
  INNER LAYER 3 w0.076: v3(35.64,27.4) 35.02,26.77 35.02,24.55 34.76,24.3 34.76,23.4 34.32,22.95 34.32,22.35 32.16,20.2 32.16,19.8 32.16,18.55 28.36,14.74 26.78,14.74 25.96,13.92 v7(25.63,13.92)
  INNER LAYER 5 w0.076: 37.94,31.39 35.72,29.16 35.72,27.45 35.66,27.4 v3(35.64,27.4)
  INNER LAYER 8 w0.076: v1(25.96,14.24) 25.87,14.24 25.63,13.99 v7(25.63,13.92)
  BOTTOM w0.076: 25.99,14.24 v1(25.96,14.24)
SPMI_CLK: length 8.9
  INNER LAYER 5 w0.076: 37.36,31.71 35.22,29.56 35.22,27.95 v7(35.11,27.85)
  INNER LAYER 8 w0.076: v7(35.11,27.85) 33.65,27.85 32.71,26.91 32.71,26.4 32.46,26.15 v8(32.46,26.02)
  BOTTOM w0.076: v8(32.46,26.02) 32.46,25.94 U11.50
SPMI_DATA: length 8.6
  INNER LAYER 5 w0.076: v7(34.84,28.23) 35.06,28.46 35.06,29.71 37.22,31.87
  INNER LAYER 8 w0.076: v9(32.07,26.04) 32.1,26.04 32.56,26.5 32.56,26.97 33.59,28 34.61,28 v7(34.84,28.23)
UIM_CLK_R: length 39.2
  TOP w0.076: v6(6.56,33.91) 6.46,34.01 5.85,34.01
  INNER LAYER 3 w0.076: v6(6.56,33.91) v3(6.79,33.69)
  INNER LAYER 5 w0.1: 36.52,43.8 36.41,43.68 35.42,43.68 35.05,44.05 35.04,44.05 v7(34.53,44.55) 33.83,44.55 32.63,45.75 21.21,45.75 18.74,43.29 13.33,43.29 7.23,37.19 7.23,34.33 6.91,34.01 6.91,33.81 v3(6.79,33.69)
  INNER LAYER 8 w0.1: v7(34.53,44.55) 34.74,44.76 v1(34.81,44.76)
  BOTTOM w0.1: TP82.1 35.01,44.56 v1(34.81,44.76)
UIM_DATA_R: length 42.1
  INNER LAYER 3 w0.076: v6(6.51,32.91) 6.61,32.91 v3(6.81,33.11)
  INNER LAYER 5 w0.1: v3(6.81,33.11) 7.51,33.81 7.51,37.23 13.4,43.11 18.81,43.11 21.27,45.57 32.31,45.57 33.86,44.02 v7(34.35,44.02) 34.5,43.87 34.98,43.87 35.35,43.5 36.47,43.5 36.6,43.62
  INNER LAYER 8 w0.1: v7(34.35,44.02) 34.57,44.02 35.67,45.12 v1(35.67,45.33)
  BOTTOM w0.1: TP80.1 36.9,46.56 v1(35.67,45.33)
UIM_DETECT_F: length 48.2
  TOP w0.076: R6663.2 32.41,37.07 33.05,37.07 v6(33.16,36.96) ; 5.85,29.61 6.26,29.61 v6(6.46,29.81)
  INNER LAYER 3 w0.076: v3(6.81,31.01) 6.46,30.66 v6(6.46,29.81) ; v3(33.26,33.21) 33.61,33.56 33.61,34.31 33.03,34.9 33.03,36.82 v6(33.16,36.96) 33.16,37.01 33.41,37.26 33.41,39.96 34.13,40.68 34.13,42.53 36.45,44.85 36.45,48.2 v3(36.61,48.36)
  INNER LAYER 5 w0.076: v3(33.26,33.21) 33.11,33.36 32.51,33.36 30.67,31.52 24.31,31.52 24.2,31.62 7.43,31.62 v3(6.81,31.01)
  INNER LAYER 8 w0.076: v2(36.76,48.71) 36.61,48.56 v3(36.61,48.36)
  INNER LAYER 9 w0.076: v1(37.06,48.56) 36.91,48.71 v2(36.76,48.71)
UIM_PWR_R: length 42.6
  TOP w0.3: 5.85,30.71 6.11,30.71 v6(6.26,30.86)
  INNER LAYER 3 w0.3: v3(6.71,31.46) 6.6,31.46 6.26,31.12 v6(6.26,30.86)
  INNER LAYER 5 w0.3: v3(6.71,31.46) 8.16,32.91 8.46,32.91 8.61,33.06 8.61,37.48 13.58,42.45 19.45,42.45 19.6,42.3 29.18,42.3 29.47,42.3 29.71,42.06 31.66,42.06 31.9,42.3 32.19,42.3 36.22,42.3 v7(37.07,43.15) 37.12,43.1 37.9,43.1 37.97,43.18
  INNER LAYER 8 w0.3: v3(6.71,31.46) 7,31.75 v1(7.11,31.75) ; v7(37.07,43.15) 37.03,43.2 37.03,43.34 37.16,43.48 37.16,43.66 v1(37.01,43.81)
  BOTTOM w0.3: v1(37.01,43.81) 37.23,44.03 37.23,44.39 TP79.1
UIM_RESET_R: length 43.4
  INNER LAYER 3 w0.076: v6(6.36,31.81) 6.5,31.94 v3(6.5,32.36)
  INNER LAYER 5 w0.1: v3(6.5,32.36) 6.5,33.53 6.47,33.55 6.47,33.82 6.5,33.84 6.5,33.84 7.06,34.4 7.06,37.27 13.25,43.46 18.66,43.46 21.13,45.93 33.22,45.93 v7(34.15,45) 34.93,45 34.93,44.99 35.19,44.99 35.2,45 36.13,45 36.28,44.84 36.54,44.84 36.7,45 37.3,45 38.28,44.01
  INNER LAYER 8 w0.1: v1(34.46,45.36) 34.46,45.31 v7(34.15,45)
  BOTTOM w0.1: v1(34.46,45.36) 35.06,45.96 TP81.1
USB2_HS_D_M: length 30
  INNER LAYER 5 w0.076: v3(9.13,17.18) 9.03,17.28 9.03,17.4 9.17,17.53 9.39,17.53 9.84,17.08 10.02,17.08 arc(10.08,17.05) 10.11,16.99 10.11,16.97 arc(10.2,16.88) 10.29,16.97 10.29,16.99 arc(10.31,17.05) 10.37,17.08 29.77,17.08 35.51,11.34
  INNER LAYER 8 w0.076: v3(9.13,17.18) 9.13,17.03 v1(9.28,16.88)
USB2_HS_D_P: length 30.2
  INNER LAYER 5 w0.076: v3(8.63,17.18) 8.83,17.38 8.83,17.48 9.08,17.73 9.47,17.73 9.92,17.29 29.85,17.29 35.59,11.55
  INNER LAYER 8 w0.076: v3(8.63,17.18) 8.78,17.03 v1(8.78,16.88)
USB_HUB1_DN: length 49.3
  TOP w0.076: R6654.1 26.24,48.41 25.9,48.06 24.91,48.06 24.81,48.16 v6(24.81,48.21)
  INNER LAYER 3 w0.076: v6(24.81,48.21) 24.72,48.11 24.25,48.11 23.6,48.76 17.72,48.76 14.11,45.16 11.15,45.16 7.5,41.51 7.5,17.22 8.43,16.28 8.96,16.28 9.03,16.21 9.03,15.96 9.01,15.93 v3(8.93,15.93)
  INNER LAYER 8 w0.076: v1(9.28,15.88) 9.23,15.93 v3(8.93,15.93)
USB_HUB1_DP: length 49.3
  TOP w0.076: R6653.1 26.31,47.51 26.06,47.26 25.94,47.26 25.86,47.34 25.86,47.76 25.76,47.86 24.81,47.86 24.81,47.86 v6(24.81,47.81)
  INNER LAYER 3 w0.076: v6(24.81,47.81) 24.71,47.91 24.16,47.91 23.51,48.56 17.8,48.56 14.2,44.96 11.23,44.96 7.7,41.43 7.7,17.3 8.52,16.49 9.04,16.49 9.05,16.48 9.23,16.48 v3(9.58,16.13)
  INNER LAYER 8 w0.076: v3(9.58,16.13) 9.58,16.08 v1(9.78,15.88)
USB_HUB2_DN: length 43
  INNER LAYER 3 w0.076: 11.61,19.17 11.61,17.95 11.25,17.59 11.03,17.59 10.96,17.66 10.96,17.86 v3(10.98,17.88) ; 11.61,19.17 11.73,19.29 ; 11.61,19.17 11.73,19.29 ; 11.73,19.29 12.45,20.01 12.45,20.1 12.45,28.69 11.8,29.33 11.8,36.4 12.76,37.36 12.76,42.31 17.38,46.93 19.52,46.93 19.95,47.36 19.95,47.56 v7(19.74,47.77)
  INNER LAYER 8 w0.076: v1(10.78,17.28) 10.73,17.33 10.73,17.63 v3(10.98,17.88)
  INNER LAYER 8 w0.1: v1(19.56,48.08) 19.56,47.98 19.74,47.8 v7(19.74,47.77)
  BOTTOM w0.076: v1(10.78,17.28) 10.73,17.23 10.73,17.13 U6838.A5
  BOTTOM w0.1: USB1.2 20.07,50.86 20.25,50.67 20.25,49.84 20,49.59 19.59,49.59 TP69.1 19.64,49.31 20.05,48.9 20.05,48.48 19.56,47.98
USB_HUB2_DP: length 43.3
  INNER LAYER 3 w0.076: v7(20.26,47.72) 20.26,47.68 20.16,47.59 20.16,47.28 20.07,47.19 20.07,47.19 19.6,46.72 17.46,46.72 12.97,42.23 12.97,37.28 12.01,36.32 12.01,29.42 12.65,28.77 12.65,20.18 12.65,19.93 11.81,19.09 11.81,17.86 11.33,17.38 10.78,17.38 10.43,17.74 v3(10.4,17.71)
  INNER LAYER 8 w0.076: v3(10.4,17.71) 10.42,17.71 10.53,17.6 10.53,17.48 v1(10.48,17.43)
  INNER LAYER 8 w0.1: v7(20.26,47.72) 20.3,47.72 v1(20.56,47.98)
  BOTTOM w0.076: U6838.A6 v1(10.48,17.43)
  BOTTOM w0.1: USB1.3 20.72,50.94 20.51,50.74 20.51,49.81 21.01,49.31 TP70.1 21.19,49.19 20.67,49.19 20.41,48.93 20.41,48.13 v1(20.56,47.98)
USB_HUB_PW_EN: length 14
  TOP w0.076: U3702.4 33.24,30.63 v6(33.41,30.8)
  INNER LAYER 3 w0.076: v3(33.71,22.41) 33.91,22.61 33.91,24.26 34.1,24.45 34.23,24.45 34.61,24.83 34.61,27.88 33.96,28.53 33.96,30.06 33.41,30.61 v6(33.41,30.8)
  INNER LAYER 5 w0.076: v3(33.71,22.41) 34.17,21.95 36.6,21.95
USB_HUB_RST_R: length 29.8
  INNER LAYER 5 w0.076: 29.24,5.48 29.12,5.36 28.52,5.36 28.2,5.03 22.24,5.03 20.53,6.74 20.53,8.34 19.09,9.78 17.74,9.78 16.63,10.88 15.7,10.88 v3(15.68,10.9) 15.63,10.86 15.63,10.68 15.43,10.48 8.72,10.48 v3(8.38,10.83)
  INNER LAYER 8 w0.1: v3(8.38,10.83) 8.38,10.83 8.53,10.98 8.53,12.68 9.63,13.78 9.63,14.28 9.73,14.38 v1(9.78,14.38) ; v1(15.46,11.52) 15.41,11.52 15.42,11.51 15.42,11.44 15.63,11.22 15.63,10.95 v3(15.68,10.9)
USB_VDD33: length 15.3
  INNER LAYER 5 w0.3: 29.12,5.95 28.94,5.77 28.73,5.77 28.71,5.78 25.46,5.78 25.24,5.57 22.35,5.57 20.98,6.93 20.98,8.56 19.11,10.43 18.43,10.43 v3(17.88,10.98)
  INNER LAYER 8 w0.3: v1(18.2,11.56) 18.19,11.56 18.08,11.46 18.08,11.18 v3(17.88,10.98)
V_LEDA: length 12.6
  INNER LAYER 9 w0.3: v1(41.83,49.73) 41.83,49.52 ; v1(41.83,49.73) 41.82,49.74 v1(41.82,50.27) ; v1(41.83,49.73) 41.84,49.72 v1(41.84,49.08) ; v1(34.34,41.57) 34.68,41.57 v1(34.69,41.58) 34.69,42.39 ; 34.69,42.06 35.19,42.56 38.16,42.56 39.06,43.46 39.06,46.76
  BOTTOM w0.3: PS3.2 35.66,41.56 C6283.2
  vias: v1(35.15,41.58)
VPH_PWR: length 36.1
  INNER LAYER 3 w0.25: 22.93,5.58 22.63,5.88 22.63,6.63 22.48,6.78 v3(22.48,6.88)
  INNER LAYER 5 w0.25: v3(22.48,6.88) 22.38,6.98 22.38,8.88 22.28,8.88 21.78,9.38 21.78,10.83 21.43,11.18 21.43,12.63 21.61,12.81 21.61,13 21.38,13.22 21.38,13.55 21.61,13.78 21.83,13.78 21.83,14.78 20.78,15.83 v3(20.68,15.83)
  INNER LAYER 8 w0.2: v3(21.13,15.83) 21.61,15.36 v1(21.69,15.36)
  INNER LAYER 8 w0.3: v8(30.69,22.87) 30.48,23.08 v7(30.48,23.32) 30.64,23.16 v8(30.79,23.16) 30.79,22.97 v8(30.69,22.87) ; v8(30.69,22.87) 30.81,22.87 v7(31.03,22.65) ; v1(34.24,27.39) 34.24,27.03 33.98,26.77 33.98,26.69 33.74,26.44 33.66,26.44 33.56,26.35 33.5,26.35 v9(33.29,26.14) 33.12,25.97 v7(33.12,25.84) 33.03,25.74 32.89,25.74 v9(32.82,25.67) ; v3(20.73,16.33) 20.83,16.43 20.83,16.98 21.13,17.28 21.83,17.28 ; v8(28.83,23.77) 28.83,23.79 v7(29.09,24.05) ; v8(30.83,26.78) 30.83,27.14 v7(30.9,27.22) 30.88,27.25 v8(30.88,27.61) 31.06,27.8 v7(31.19,27.8) 31.05,27.94 v8(30.86,27.94)
  INNER LAYER 9 w0.2: v8(30.86,27.94) 30.83,27.9 v8(30.83,26.78) 30.98,26.63 v1(30.98,26.54) 30.98,26.44 30.83,26.29 v1(30.83,26.29)
  INNER LAYER 9 w0.3: v4(31.82,25.3) v4(32.07,25.54) 32.39,25.54 32.52,25.67 v9(32.82,25.67)
  BOTTOM w0.075: 29.33,23.81 29.33,24.31 ; 29.33,26.29 29.33,26.78
  BOTTOM w0.076: 28.79,26.23 28.83,26.28 C223.1 ; v8(30.83,26.78) 30.83,27.56 v8(30.88,27.61) ; U11.56 U11.62 30.08,26.54 U11.67 ; 28.89,24.36 29.79,24.36 29.84,24.31 ; v4(32.07,25.54) 32.5,25.54 32.63,25.67 v9(32.82,25.67)
  BOTTOM w0.15: 29.33,24.31 29.09,24.56 ; 28.83,27.06 28.89,27 C223.1
  BOTTOM w0.2: 30.88,27.95 v8(30.88,27.61) ; U11.7 30.09,24.06
  BOTTOM w0.203: 29.84,24.3 30.09,24.06 29.84,23.81 28.83,23.81 ; 29.87,26.78 29.83,26.82 29.75,26.82 29.79,26.78 ; 28.66,26.02 29.06,26.43 ; v4(31.82,25.3) v4(32.07,25.54)
  BOTTOM w0.25: v4(30.83,24.31) U11.9 31.07,24.06 v1(30.83,23.81) 30.83,23.01 v8(30.69,22.87)
  BOTTOM w0.254: U11.56 29.22,26.29 29.17,26.23 28.79,26.23
  BOTTOM w0.3: v1(30.32,22.01) 30.32,22.38 30.7,22.76
  vias: v1(22.18,16.83) v1(22.48,16.53) v1(22.59,17.23) v1(22.54,16.88) v1(22.89,17.08) v1(22.93,17.43) v1(23.34,17.28) v2(22.18,16.83) v2(22.48,16.53) v2(22.59,17.23) v2(22.54,16.88) v2(22.89,17.08) v2(22.93,17.43) v2(23.34,17.28) v3(20.28,16.28) v3(20.23,15.83) v3(21.18,16.33) v3(22.03,6.93) v3(22.43,6.43) v3(22.88,6.83) v3(22.88,6.38) v3(23.28,6.53) v4(30.41,22.41) v7(28.4,24.14) v7(28.5,26.7) v7(28.56,25.55) v7(28.53,25.09) v7(28.82,27.2) v7(28.99,25.55) v7(28.99,25.1) v8(28.74,26.79) v8(28.77,26.45) v8(28.76,26.19) v8(28.78,25.87) v8(28.76,24.67) v8(28.74,24.39) v8(28.74,24.07) v8(28.95,26.29) v8(29.01,24.41) v8(29.1,25.88) v8(29.04,24.68) v8(29.12,26.81) v8(29.13,26.52) v8(29.16,26.16) v8(29.13,23.62) v8(29.33,25.96) v8(29.47,23.7) v8(30.66,22.61) v8(31.06,23.11)
VREG_5V: length 42.7
  TOP w0.4: U3702.5 31.34,29.54 32.26,30.46 C4608.1 ; C4608.1 32.56,31.01 v6(32.58,31.03) v6(32.58,31.38) 32.59,31.68 v5(32.53,31.73) 32.26,31.46 C4608.1
  INNER LAYER 3 w0.4: 32.43,32.43 32.43,31.86 v6(32.54,31.75) ; v6(32.54,31.75) 32.54,32.32 32.49,32.37 ; v6(32.54,31.75) 32.59,31.71 v6(32.59,31.38) v6(32.58,31.03)
  INNER LAYER 3 w0.5: v3(32.81,41.11) v3(32.36,41.11) 32.8,40.67 32.8,37.91 32.66,37.77 32.66,34.61 32.42,34.37 32.42,33.94 32.43,33.93 32.43,32.43 32.49,32.37
  INNER LAYER 8 w0.5: v3(32.36,41.11) 32.36,41.42 32.41,41.47 32.41,41.33 32.37,41.29 32.37,41.12 v3(32.36,41.11) ; v3(32.36,41.11) v3(32.81,41.11) 33.74,42.04 33.74,42.04
  INNER LAYER 8 w0.8: 32.41,41.47 33.17,41.47 33.74,42.04 34.9,42.04 34.9,42.04 36.47,42.04 36.81,41.7 37.24,41.7 40.83,41.7 ; 32.36,41.42 21.25,41.42 19.26,39.43 v1(19.26,39.39)
  BOTTOM w0.8: U3704.5 17.75,39.39 v1(19.26,39.39)
  vias: v1(18.46,39.56) v1(18.46,39.21) v1(18.86,39.61) v1(18.86,39.26) v1(19.56,39.66) v1(19.61,39.26) v1(74.36,18.17) v2(18.46,39.56) v2(18.46,39.21) v2(18.86,39.61) v2(18.86,39.26) v2(19.56,39.66) v2(19.61,39.26) v2(48.52,39.78) v2(48.64,40.12) v2(48.83,39.89) v2(49.16,40.12) v2(49.14,39.79)
VREG_HUB_1P2: length 46
  INNER LAYER 8 w0.25: v1(12.73,11.03) 12.73,12.43 v1(12.28,12.88) ; 13.96,10.46 13.96,10.26 13.63,9.93 11.54,9.93 10.77,9.17 7.65,9.17 6.88,9.93 6.88,10.78 v1(6.98,10.88) ; 13.96,10.46 16.59,10.46 18.11,11.99 18.11,13.37 v1(18.18,13.43) ; 13.96,10.46 v1(13.38,11.03) ; v1(8.78,14.38) 8.63,14.23 v1(6.95,14.23) 5.33,15.85 5.33,17.83 5.73,18.23 5.73,18.53 6.08,18.88 6.88,18.88 v2(7.13,19.13)
  INNER LAYER 9 w0.25: v1(8.78,15.88) 8.66,16.01 8.11,16.01 6.93,17.18 6.93,18.38 6.95,18.4 v1(6.95,18.48)
  INNER LAYER 9 w0.3: v1(7.33,19.83) 7.13,19.63 v2(7.13,19.13)
  BOTTOM w0.076: C6231.2 6.95,11.73 ; 6.95,12.28 6.92,12.31 C6386.1 ; C6384.1 14.12,12.58 ; C6388.1 12.78,11.05 ; 13.38,11.05 v1(13.38,11.03) C6389.1 ; C6379.1 7.53,18.27 ; C6387.1 6.95,12.98 ; C6385.1 14.12,13.23 ; 6.95,13.65 6.93,13.63 C6381.1
  BOTTOM w0.25: 6.95,12.98 7,13.03 7.58,13.03 7.93,13.38 U6838.H10 ; 6.95,12.98 6.95,11.73 6.98,11.7 v1(6.98,10.88) B30.1 ; 6.95,12.98 v1(6.95,14.23) ; v1(18.18,13.43) 18.18,14.03 U3708.1 ; 12.78,11.05 13.38,11.05 13.48,11.15 13.48,12.18 13.88,12.58 14.12,12.58 14.12,13.23 13.97,13.38 U6838.H1 ; 7.53,18.27 7.53,18 7.52,17.98 7.52,17.6 8.23,16.88 U6838.A10
  BOTTOM w0.3: v1(7.33,19.83) 7.33,19.73 7.13,19.53 7.13,19.47 6.95,19.28 v1(6.95,18.48)
  BOTTOM w0.35: C6379.1 7.13,18.3 v1(6.95,18.48)
